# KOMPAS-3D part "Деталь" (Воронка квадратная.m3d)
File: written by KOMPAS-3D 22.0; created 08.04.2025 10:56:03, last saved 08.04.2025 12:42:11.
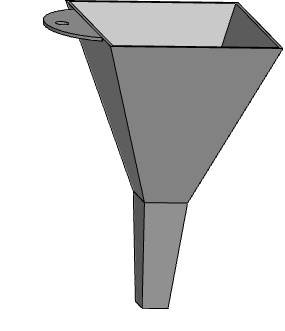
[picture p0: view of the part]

Document properties: Автор: Admin; Полное имя файла: D:\28.11.2016\Абилимпикс\2025\Воронка квадратная.m3d

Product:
- Body: Тело 8
    Масса: 0.182888
- Body: Тело 9
    Масса: 0.182888
- Part/product: Деталь
    Масса: 0.225679

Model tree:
1. Эскиз:5
2. Смещенная плоскость:2
     Расстояние = 80
3. Эскиз:6
4. Элемент по сечениям:5
5. Эскиз:7  (with: Элемент по сечениям:5)
6. Эскиз:8  (with: Элемент по сечениям:5)
7. Элемент по сечениям:6
8. Смещенная плоскость:3  (with: Элемент по сечениям:5)
     Расстояние = 50
9. Эскиз:9
10. Элемент по сечениям:7
11. Эскиз:10  (with: Элемент по сечениям:7)
12. Элемент по сечениям:8
13. Эскиз:11  (with: Элемент по сечениям:5)
14. Элемент выдавливания:7
     Расстояние 2 = 1.5
15. Элемент выдавливания:8  (with: Элемент выдавливания:7, Элемент по сечениям:5)
     Расстояние 1 = 0.28125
